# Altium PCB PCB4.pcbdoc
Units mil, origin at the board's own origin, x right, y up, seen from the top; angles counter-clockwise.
Board outline 4005 x 2740 mil, 2 copper layers (Top Layer, Bottom Layer), stack 2.757 mil thick; 56 components, 38 nets, 174 pads, 21 vias.
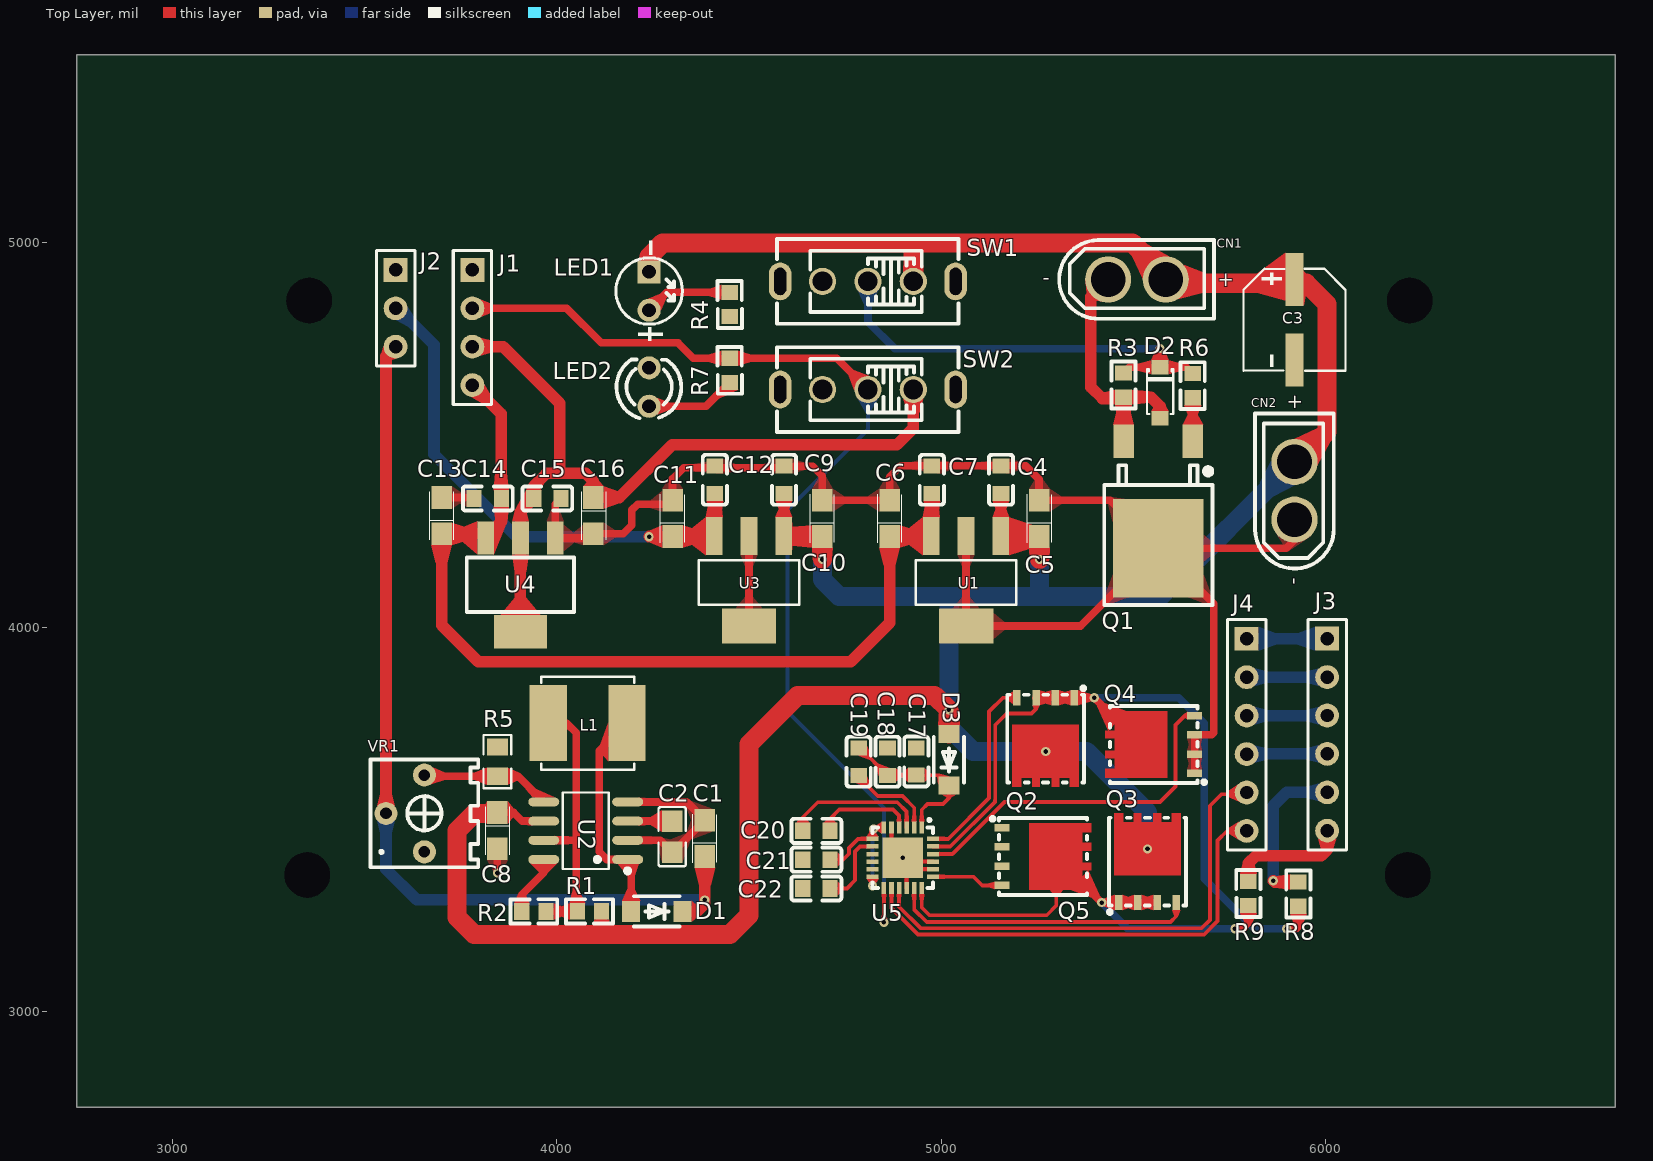
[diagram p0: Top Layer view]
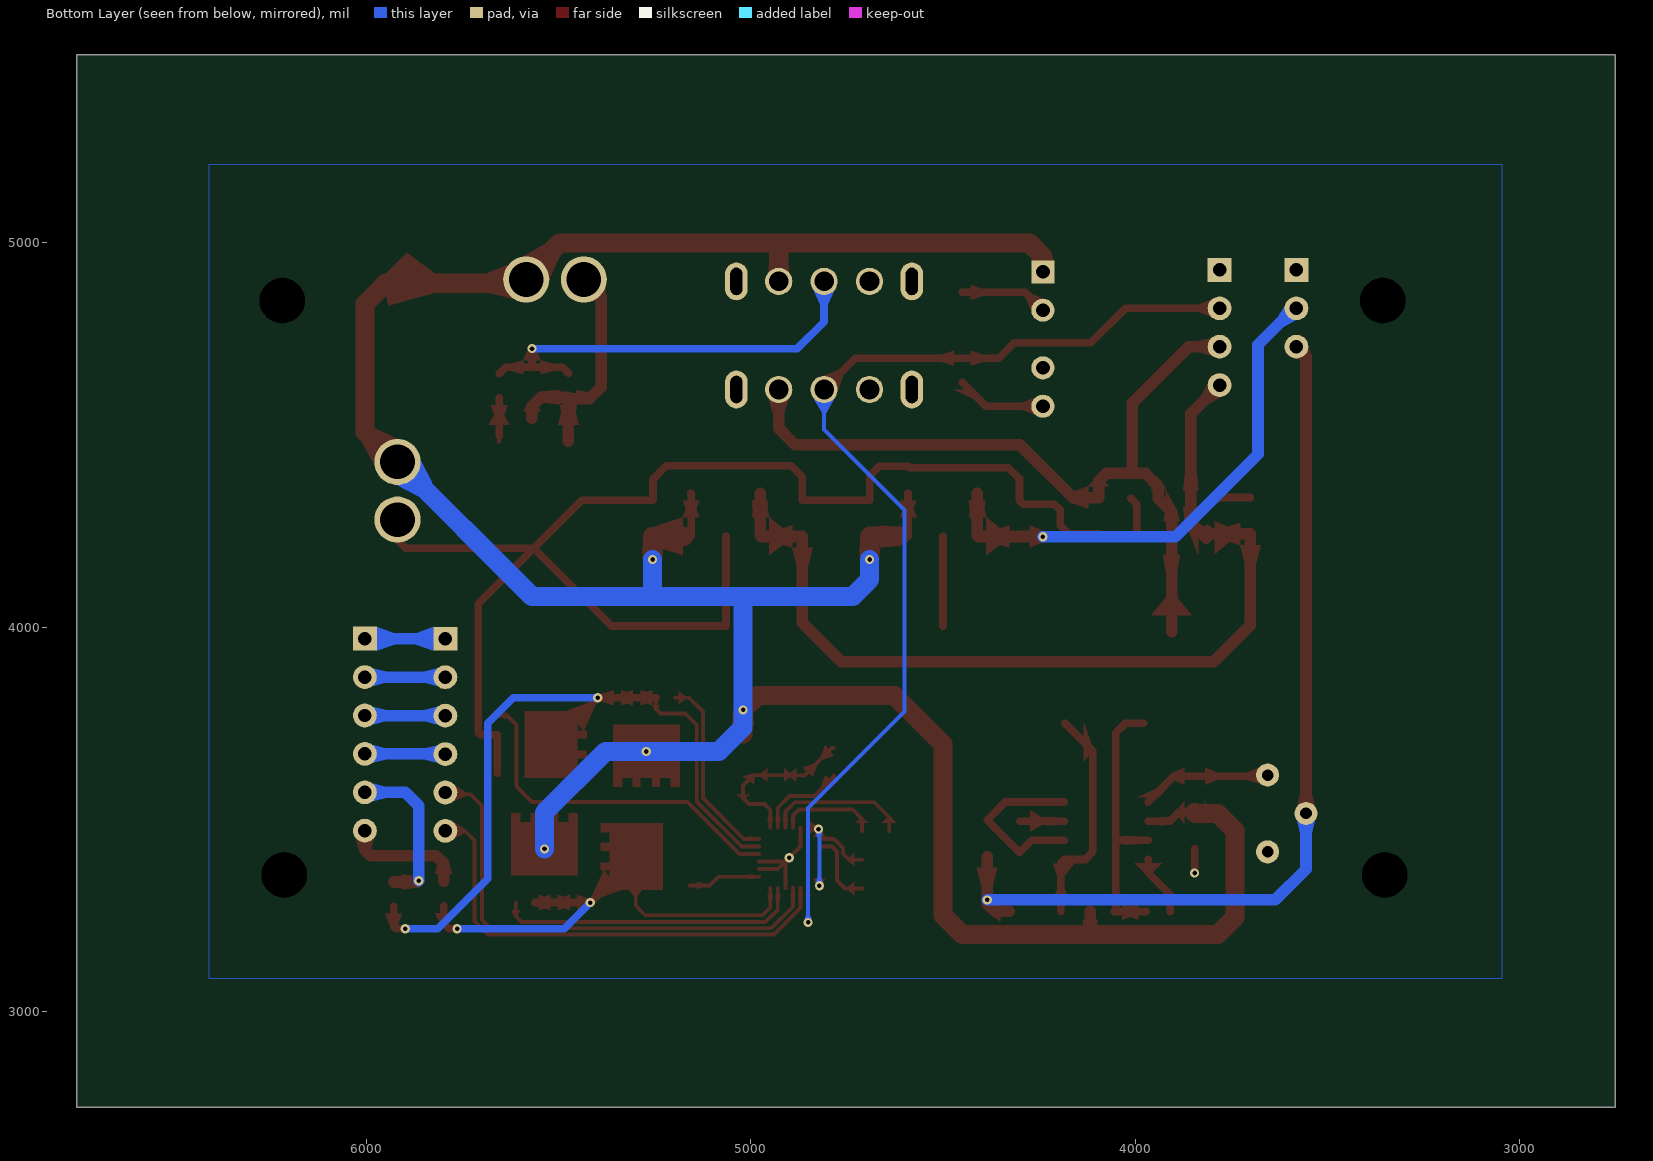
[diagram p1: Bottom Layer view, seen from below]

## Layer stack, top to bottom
Top Layer: signal copper 1.379
Bottom Layer: signal copper 1.378

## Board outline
6755,2750 2750,2750 2750,5490 6755,5490
cut-out: 3414.06,4850 ccw(c3355,4850) 3295.94,4850 ccw(c3355,4850)
cut-out: 6279.06,4850 ccw(c6220,4850) 6160.94,4850 ccw(c6220,4850)
cut-out: 6274.06,3355 ccw(c6215,3355) 6155.94,3355 ccw(c6215,3355)
cut-out: 3409.06,3355 ccw(c3350,3355) 3290.94,3355 ccw(c3350,3355)

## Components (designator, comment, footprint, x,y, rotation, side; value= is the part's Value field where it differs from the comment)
C1 "10u" CASE-A_3216 4385,3450 r90 top
C2 "470pF" C0805 4300,3454.45 r90 top
C3 "220uF" CAP-SMD_BD6.3-L6.6-W6.6-FD 5920,4800 r270 top
C4 "100nf" C0603 5156.02,4383.58 r270 top
C5 "10u" CASE-A_3216 5256.02,4283.14 r90 top
C6 "10u" CASE-A_3216 4866.02,4283.14 r90 top
C7 "100nf" C0603 4976.02,4383.58 r270 top
C8 "10u" CASE-A_3216 3845,3470 r270 top
C9 "100nf" C0603 4591.02,4383.58 r270 top
C10 "10u" CASE-A_3216 4691.02,4283.14 r90 top
C11 "10u" CASE-A_3216 4301.02,4283.14 r90 top
C12 "100nf" C0603 4411.02,4383.58 r270 top
C13 "10u" CASE-A_3216 3700,4290 r90 top
C14 "100nf" C0603 3820,4335 r0 top
C15 "100nf" C0603 3975,4335 r180 top
C16 "10u" CASE-A_3216 4095,4290 r270 top
C17 "100nF" C0603 4935.44,3650 r270 top
C18 "10uF" C0603 4860.44,3649.57 r270 top
C19 "16V 1uF" C0603 4785.44,3649.57 r270 top
C20 "100nF" C0603 4675.44,3469.57 r0 top
C21 "6.3V 1uF" C0603 4675.44,3394.57 r180 top
C22 "6.3V 1uF" C0603 4675.44,3319.57 r180 top
CN1 "XT30UPB-M" CONN-TH_XT30UPB-M 5510,4905 r0 top
CN2 "XT30UPB-M" CONN-TH_XT30UPB-M 5920,4355 r90 top
D1 "1N5819HW-7-F" SOD-123_L2.8-W1.8-LS3.7-FD 4260,3260 r0 top
D2 "BZT52C16_C216724" SOD-123_L2.8-W1.8-LS3.7-RD 5570,4610 r270 top
D3 "1N5819HW-7-F" SOD-123_L2.8-W1.8-LS3.7-FD 5020.44,3654.57 r270 top
J1 "HDR-M-2.54_1x4" HDR-M-2.54_1X4 3780,4780 r270 top
J2 "HDR-M-2.54_1x3" HDR-M-2.54_1X3 3580,4830 r270 top
J3 "HDR-M-2.54_1x6" HDR-M-2.54_1X6 6005,3720 r270 top
J4 "HDR-M-2.54_1x6" HDR-M-2.54_1X6 5795.44,3719.57 r270 top
L1 "470uH" IND-SMD_L6.0-W6.0_SWPA6045S 4080,3750 r180 top
LED1 "TJ-L3FYTGHGMCGLFLC2G-A5" LED-TH_BD3.9-P2.54-FD 4240,4875 r270 top
LED2 "TJ-L3FYTXHAMCGLFLC0A-A5" LED-TH_BD3.0-P2.54-FD 4240,4625 r90 top
Q1 "IRLR7843TRPBF" TO-252-2_L6.5-W6.1-P4.58-LS10.0-TR 5565.51,4344.55 r0 top
Q2 "TPH1R403NL" POWERVDFN-8_L6.2-W5.2-P1.27-LS6.0-BL 5272.24,3746.26 r180 top
Q3 "TPH1R403NL" POWERVDFN-8_L6.2-W5.2-P1.27-LS6.0-BL 5537.24,3352.88 r0 top
Q4 "TPH1R403NL" POWERVDFN-8_L6.2-W5.2-P1.27-LS6.0-BL 5590.32,3694.57 r90 top
Q5 "TPH1R403NL" POWERVDFN-8_L6.2-W5.2-P1.27-LS6.0-BL 5228.74,3402.76 r270 top
R1 "0.22R" R0603 4085,3260 r0 top
R2 "180R" R0603 3939.97,3259.8 r0 top
R3 "100k" R0603 5475,4630 r90 top
R4 "510" R0603 4450,4840 r90 top
R5 "1k" R0805 3845,3650 r270 top
R6 "1k" R0603 5655,4628.51 r90 top
R7 "330" R0603 4450,4668.51 r90 top
R8 "1k" R0603 5930,3305 r270 top
R9 "1k" R0603 5800,3306.49 r270 top
SW1 "SS-12F44-G5" SW-TH_SS-12F44-G5 4809.54,4900 r180 top
SW2 "SS-12F44-G5" SW-TH_SS-12F44-G5 4809.54,4618.54 r180 top
U1 "LM2940S-5.0" SOT-223-3_L6.5-W3.4-P2.30-LS7.0-BR 5065,4120 r90 top
U2 "MC34063ADR" SOIC-8_L4.9-W3.9-P1.27-LS6.0-BL 4075,3470 r90 top
U3 "LM2940S-5.0" SOT-223-3_L6.5-W3.4-P2.30-LS7.0-BR 4500,4120 r90 top
U4 "AMS1117-3.3_C347222" SOT-223_L6.7-W3.5-P2.30-BR 3905,4110 r90 top
U5 "DRV8701ERGET" VQFN-24_L4.0-W4.0-P0.50-LS4.0-BL-EP 4900.48,3399.51 r180 top
VR1 "10kΩ" RES-ADJ-TH_3362P 3605,3515 r90 top

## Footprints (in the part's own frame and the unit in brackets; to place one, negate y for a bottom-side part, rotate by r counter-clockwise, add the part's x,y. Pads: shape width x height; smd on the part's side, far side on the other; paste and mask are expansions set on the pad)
C0603 [mm]
  rect 1x1.1 smd: 1(-0.9,0) 2(0.9,0)
  silkscreen extent -1.65,-0.8 1.65,0.8
C0805 [mm]
  rect 1.41x1.35 smd: 1(-1.03,0) 2(1.03,0)
  silkscreen extent -1.96,-0.9 1.96,0.9
CAP-SMD_BD6.3-L6.6-W6.6-FD [mm]
  rect 3.5x1.2 smd: 1(-2.67,0) 2(2.67,0)
  silkscreen extent -3.38,-3.38 3.38,3.38
CASE-A_3216 [mil]
  rect 59.05x53.5 smd: 1(-47.24,0) 2(47.24,0)
  silkscreen extent -63,-32 63,32
CONN-TH_XT30UPB-M [mil]
  round 120 hole 90: 1(-74.99,0) 2(75.01,0)
  silkscreen extent -202,-102 201,102
HDR-M-2.54_1X3 [mil]
  rect 62x62 hole 35: 1(-100,0)
  round 62 hole 35: 2(0,0) 3(100,0)
  silkscreen extent -150,-50 150,50
HDR-M-2.54_1X4 [mil]
  rect 62x62 hole 35: 1(-150,0)
  round 62 hole 35: 2(-50,0) 3(50,0) 4(150,0)
  silkscreen extent -200,-50 200,50
HDR-M-2.54_1X6 [mil]
  rect 62x62 hole 35: 1(-250,0)
  round 62 hole 35: 2(-150,0) 3(-50,0) 4(50,0) 5(150,0) 6(250,0)
  silkscreen extent -300,-50 300,50
IND-SMD_L6.0-W6.0_SWPA6045S [mm]
  rect 2.474x5.02 smd: 1(-2.603,0) 2(2.603,0)
  silkscreen extent -3.08,-3.08 3.08,3.08
LED-TH_BD3.0-P2.54-FD [mil]
  round 60 hole 36: 1(-50,0) 2(50,0)
  silkscreen extent -81,-84 72,85
LED-TH_BD3.9-P2.54-FD [mil]
  rect 60x60 hole 36: 1(-50,0)
  round 60 hole 36: 2(50,0)
  silkscreen extent -130,-87 130,87
POWERVDFN-8_L6.2-W5.2-P1.27-LS6.0-BL [mm]
  rect 0.5x1 smd: 1(-1.905,-1.775) 2(-0.635,-1.775) 3(0.635,-1.775) 4(1.905,-1.775)
  Top Layer region: -2.2,0.025 -2.2,4.125 -1.6,4.125 -1.6,3.525 -0.9,3.525 -0.9,4.125 -0.4,4.125 -0.4,3.525 0.4,3.525 0.4,4.125 0.9,4.125 0.9,3.525 1.6,3.525 1.6,4.125 2.2,4.125 2.2,0.025
  silkscreen extent -2.61,-2.53 2.54,3.83
R0603 [mm]
  rect 1x1.1 smd: 1(-0.8,0) 2(0.8,0)
  silkscreen extent -1.55,-0.8 1.55,0.81
R0805 [mil]
  rect 44.59x54.21 smd: 1(-38.04,0) 2(38.04,0)
  silkscreen extent -69,-36 69,36
RES-ADJ-TH_3362P [mil]
  round 60 hole 30: 1(-100,-50) 2(0,50) 3(100,-50)
  silkscreen extent -140,-190 140,90
SOD-123_L2.8-W1.8-LS3.7-FD [mm]
  rect 1.2x1.4 smd: 1(-1.7,0) 2(1.7,0)
  silkscreen extent -1.5,-1 1.5,1
SOD-123_L2.8-W1.8-LS3.7-RD [mm]
  rect 0.95x1.15 smd: 1(-1.692,0) 2(1.692,0)
  silkscreen extent -1.58,-0.87 1.41,0.87
SOIC-8_L4.9-W3.9-P1.27-LS6.0-BL [mm]
  oval 0.588x2.045 smd: 1(-1.905,-2.772) 2(-0.635,-2.772) 3(0.635,-2.772) 4(1.905,-2.772) 5(1.905,2.772) 6(0.635,2.772) 7(-0.635,2.772) 8(-1.905,2.772)
  silkscreen extent -2.8,-2.92 2.53,1.52
SOT-223-3_L6.5-W3.4-P2.30-LS7.0-BR [mm]
  rect 2.5x1.1 smd: 1(2.97,-2.3) 2(2.97,0) 3(2.97,2.3)
  rect 2.34x3.6 smd: 4(-2.97,0)
  silkscreen extent -1.57,-3.33 1.37,3.33
SOT-223_L6.7-W3.5-P2.30-BR [mm]
  rect 2.2x1.1 smd: 1(3.099,-2.3) 2(3.099,0) 3(3.099,2.3)
  rect 2.2x3.5 smd: 4(-3.099,0)
  silkscreen extent -1.8,-3.55 1.8,3.55
SW-TH_SS-12F44-G5 [mm]
  round 1.8 hole 1.3: 1(-3,0) 2(0,0) 3(3,0)
  oval 1.5x2.5 hole 0.8 slot 1.8 at 90 deg: 4(5.8,0) 5(-5.8,0)
  silkscreen extent -6,-2.8 6,2.8
TO-252-2_L6.5-W6.1-P4.58-LS10.0-TR [mm]
  rect 1.35x2.2 smd: 1(2.29,3.533) 3(-2.29,3.533)
  rect 6x6.5 smd: 4(0,-3.533)
  silkscreen extent -3.57,-7.3 3.57,1.95
VQFN-24_L4.0-W4.0-P0.50-LS4.0-BL-EP [mm]
  rect 0.3x0.8 smd: 1(-1.25,-1.999) 2(-0.751,-2) 3(-0.25,-2) 4(0.25,-2) 5(0.751,-2) 6(1.251,-2) 13(1.25,2) 14(0.749,2) 15(0.249,2) 16(-0.25,2) 17(-0.749,2) 18(-1.25,2)
  rect 0.8x0.3 smd: 7(2.001,-1.25) 8(2.001,-0.75) 9(2.001,-0.249) 10(2.001,0.251) 11(2.001,0.752) 12(2.001,1.251) 19(-2.001,1.25) 20(-2.001,0.75) 21(-2.001,0.251) 22(-2.001,-0.248) 23(-2.001,-0.749) 24(-2.001,-1.249)
  rect 2.7x2.7 smd: 25(0.001,-0.002)
  silkscreen extent -2,-2.6 2,2

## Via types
v1: diameter 24.02, hole 12.01, Top Layer to Bottom Layer, 21 vias

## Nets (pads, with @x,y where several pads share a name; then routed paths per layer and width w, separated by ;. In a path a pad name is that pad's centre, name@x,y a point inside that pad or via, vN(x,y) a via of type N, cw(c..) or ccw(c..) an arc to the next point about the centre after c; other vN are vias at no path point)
$1N55: R5.2 U2.5 VR1.3 | length 339.8
  Top Layer w20: VR1.3 3658.04,3611.96 R5.2 3898.89,3611.96 U2.5
$1N212: L1.2 R1.1 R2.2 U2.7 | length 715.7
  Top Layer w20: U2.7 4050,3445 ; R2.2 R1.1@4053.3,3259.8 ; L1.2 4025,3750 4050,3725 4050,3445 ; R1.1 R1.1@4053.3,3259.8 ; 4050,3445 4050,3263.1 R1.1@4053.3,3259.8
$1N213: R2.1 U2.8 | length 159
  Top Layer w20: R2.1 3908.48,3303.48 3965.85,3360.85 U2.8
$1N218: C2.2 U2.3 | length 115.9
  Top Layer w20: U2.3 C2.2
$1N221: D1.1 L1.1 U2.1 | length 586.2
  Top Layer w20: L1.1 4110,3677.52 4110,3415 4130,3395 U2.1 4193.07,3386.08 D1.1
$1N479: Q1.1 R6.1 | length 113.6
  Top Layer w10: Q1.1@5655,4497.16 5655,4484.32 Q1.1
  Top Layer w20: Q1.1@5655,4497.16 R6.1
$1N482: D2.1 R3.2 R6.2 SW1.2 | length 1135.7
  Top Layer w10: D2.1 D2.1@5576.64,4676.63
  Top Layer w20: R3.2 5490.14,4676.63 D2.1 v1(5570,4725) ; D2.1@5576.64,4676.63 5638.37,4676.63 R6.2
  Bottom Layer w20: SW1.2 4809.54,4795.46 4880,4725 v1(5570,4725)
$1N610: LED1.2 R4.2 | length 229.3
  Top Layer w20: LED1.2 4286.49,4871.49 R4.2
$1N637: LED2.1 R7.1 | length 235.7
  Top Layer w20: LED2.1 4387.99,4575 R7.1
$1N34558: C21.1 U5.6 U5.7 U5.12 | length 370.8
  Top Layer w10: C21.1 4744.57,3394.57 4760,3410 4760,3425 4783.72,3448.72 U5.7 4820,3450.43 4820,3470 4828.25,3478.25 U5.6 ; v1(4821.72,3326.72) U5.12
  Bottom Layer w10: v1(4821.72,3326.72) 4821.72,3471.72 v1(4824.19,3474.19)
$1N34565: C20.2 U5.4 | length 258.6
  Top Layer w10: C20.2 4710.87,3500.87 4735,3525 4875,3525 4890.62,3509.38 U5.4
$1N34566: C20.1 U5.3 | length 373.4
  Top Layer w10: C20.1 4640,3505 4679,3544 4886,3544 4910.34,3519.66 U5.3
$1N34567: C19.2 U5.2 | length 233.9
  Top Layer w10: C19.2 4785.44,3609.57 4835,3560 4900,3560 4930.02,3529.97 U5.2
$1N34568: C17.2 C18.2 C19.1 D3.2 U5.1 | length 437.8
  Top Layer w10: C19.1 4789.56,3685 C18.2 4860.87,3614.57 C17.2 4993.51,3614.57 D3.2 5020.44,3555.43 5005,3540 4965,3540 4949.69,3524.68 U5.1
$1N34570: Q2.4 U5.24 | length 502
  Top Layer w10: U5.24 5018.69,3448.69 5125,3555 5125,3780 5161.14,3816.14 Q2.4
$1N34571: Q4.4 U5.22 | length 923.9
  Top Layer w10: U5.22 5029.29,3409.29 5165,3545 5570,3545 5610,3585 5610,3745 5634.57,3769.57 Q4.4
$1N34574: Q3.4 U5.17 | length 793.5
  Top Layer w10: U5.17 4929.98,3265.03 4962.69,3232.31 5597.31,3232.31 5612.24,3247.24 Q3.4
$1N34575: Q5.4 U5.19 | length 189
  Top Layer w10: U5.19 4979.52,3350 5085,3350 5107.24,3327.76 Q5.4
ADC-0: J3.1 J4.1 | length 209.7
  Bottom Layer w30: J4.1 6004.57,3969.57 J3.1
ADC-1: J3.2 J4.2 | length 209.7
  Bottom Layer w30: J4.2 6004.57,3869.57 J3.2
ADC-2: J3.3 J4.3 | length 209.7
  Bottom Layer w30: J4.3 6004.57,3769.57 J3.3
ADC-3: J3.4 J4.4 | length 209.7
  Bottom Layer w30: J4.4 5795.87,3670 J3.4
AOUT+: Q2.1 Q2.2 Q2.3 R8.2 U5.23 | length 1960.5
  Top Layer w10: U5.23 5023.99,3428.99 5140,3545 5140,3549.43 5141,3548.37 5141,3745 5171,3775 5235,3775 5247.24,3787.24 Q2.3
  Top Layer w20: Q2.3 Q2.2 Q2.1 v1(5398.86,3816.14) 5520.44,3694.57 ; v1(5900,3215) 5925,3215 5930,3220 R8.2
  Bottom Layer w20: v1(5398.86,3816.14) 5618.86,3816.14 5685,3750 5685,3345 5815,3215 v1(5900,3215)
AOUT+OUT: J3.5 R8.1 | length 415.9
  Top Layer w30: v1(5865,3340) 5868.5,3336.5 R8.1
  Bottom Layer w30: v1(5865,3340) 5865,3535 5900,3570 J3.5
AOUT-: Q3.1 Q3.2 Q3.3 R9.2 U5.18 | length 1320.1
  Top Layer w10: U5.18 4949.68,3270.32 4970,3250 5275,3250 5300,3275 5300,3401.39
  Top Layer w20: 5298.63,3402.76 5300,3401.39 v1(5418.4,3282.99) Q3.1 Q3.2 Q3.3 ; v1(5765,3215) 5785,3215 5800,3230 R9.2
  Bottom Layer w20: v1(5418.4,3282.99) 5486.39,3215 v1(5765,3215)
AOUT-OUT: J3.6 R9.1 | length 316.5
  Top Layer w30: R9.1 5800,3385 5820,3405 5990,3405 6005,3420 J3.6
DVDD: C22.1 U5.8 | length 200.1
  Top Layer w10: C22.1 4711.3,3320 4755,3320 4776,3341 4776,3416 4789.02,3429.02 U5.8
EN: J4.6 U5.14 | length 1239.8
  Top Layer w10: U5.14 4870.98,3269.03 4940,3200 5685,3200 5720,3235 5720,3445 5745,3470 5795,3470 J4.6
GND: C1.2 C2.1 C3.2 C4.1 C5.2 C6.2 C7.1 C8.2 C9.1 C10.2 C11.2 C12.1 C13.2 C14.1 C15.1 C16.2 C17.1 C18.1 C21.2 C22.2 CN2.1 J1.1 J2.1 LED2.2 Q1.4 Q4.1 Q4.2 Q4.3 Q5.1 Q5.2 Q5.3 R4.1 R5.1 U1.2 U1.4 U2.2 U2.4 U3.2 U3.4 U4.1 U5.5 U5.16 U5.20 U5.21 U5.25 | length 5145.2
  Top Layer w10: U5.5 4870.93,3429.08 v1(4900.44,3399.57) U5.25@4910.32,3389.68 ; U5.16 U5.25@4910.32,3389.68 ; U5.21@4979.19,3389.68 U5.25@4910.32,3389.68 ; U5.20 4930.02,3369.99 U5.25@4910.32,3389.68
  Top Layer w20: C13.2 3782.32,4337.24 C14.1 ; v1(3845,3360) C8.2 ; C15.1 3995.55,4320.11 U4.1 4084.24,4232 C16.2 4172.76,4242.76 4195,4265 4195,4305 4210,4320 4290.64,4320 C11.2 4301.02,4386.02 4330,4415 4587.01,4415 C9.1 4665.99,4419.01 4691.02,4393.98 C10.2 C6.2 4866.02,4391.02 4895,4420 5220,4420 5255,4385 5255,4331.4 C5.2 5440.58,4330.38 Q1.4 ; U2.2 4268.9,3445 C2.1 4301.66,3413.9 C1.2 4337.24,3545 U2.4 ; U3.4 U3.2 ; U1.2 U1.4 5363.14,4003.07 Q1.4 ; Q4.1 Q4.2 Q4.3 5704.57,3719.57 5710,3725 5710,4060.96 Q1.4 ; CN2.1@5935,4241.57 5898.87,4205.45 Q1.4
GNDIN: CN1.1 D2.2 Q1.3 R3.1 | length 647.4
  Top Layer w30: CN1.1 5390,4860 5390,4625 5420,4595 R3.1@5475,4595 ; Q1.3 5475,4484 R3.1@5475,4595 ; D2.2 5570,4575 5546.5,4598.5 R3.1 R3.1@5475,4595
NSLEEP: J1.2 R7.2 SW2.2 U5.13 | length 2784.8
  Top Layer w10: v1(4851.27,3231.28) U5.13
  Top Layer w20: J1.2 4025,4830 4115,4740 4315,4740 4355,4700 R7.2 4728.07,4700 SW2.2
  Bottom Layer w10: SW2.2 4809.54,4514.54 4600,4305 4600,3780 4851.27,3528.72 v1(4851.27,3231.28)
PH: J4.5 U5.15 | length 1297.1
  Top Layer w10: U5.15 4890.68,3271.95 4946.31,3216.31 5678.69,3216.31 5700,3237.63 5700,3535 5730,3565 5790.87,3565 J4.5
VCC: C3.1 C4.2 C5.1 C8.1 C9.2 C10.1 CN1.2 CN2.2 D3.1 LED1.1 R1.2 SW1.1 U1.1 U2.6 U3.1 | length 8033.9
  Top Layer w20: 3815,3515 3817.24,3517.24 ; C8.1 3887.76,3517.24 3910,3495 U2.6 ; C9.2 4591.02,4237.4 U3.1 4612.54,4236.93 ; v1@4690,4175 v1(4691.02,4176.02) ; SW1.1 SW1.1@4927.65,4917.65 ; C4.2 5155.55,4347.67 U1.1 5156.57,4235.9 U1.1@5174.63,4235.9 ; v1@5255,4175 v1(5256.02,4176.02)
  Top Layer w30: 4116.18,3200 4116.49,3200.31 R1.2 ; CN1.2 CN1.2@5593.43,4905 ; 5701.27,4905 5711.27,4895
  Top Layer w50: C8.1 3842.76,3515 3815,3515 3785,3515 3740,3470 3740,3245 3785,3200 4116.18,3200 4450,3200 4500,3250 4500,3695 4627.12,3822.12 4982.88,3822.12 v1(5020.44,3784.57) D3.1 ; v1(4240,4925) 4240,4965 4275,5000 4931.95,5000 ; 4612.54,4236.93 4690,4236.93 C10.1 v1(4691.02,4176.02) ; SW1.1@4927.65,4917.65 4927.65,4995.7 4931.95,5000 ; U1.1@5174.63,4235.9 C5.1 v1(5256.02,4176.02) ; CN2.2@5935,4438.43 6005,4508.43 6005,4840.7 5950.7,4895 5711.27,4895 v1(5603.43,4895) 5593.43,4905 5498.43,5000 4931.95,5000
  Bottom Layer w50: v1(4691.02,4176.02) 4691.02,4123.98 4735,4080 5029.27,4080 ; v1(5256.02,4176.02) 5256.02,4080 ; v1(5537.24,3422.76) 5537.24,3517.76 5378.63,3676.37 v1(5272.24,3676.37) 5083.63,3676.37 5020.44,3739.57 v1(5020.44,3784.57) 5020.44,4071.16 5029.27,4080 ; CN2.2@5935,4438.43 5928.43,4438.43 5570,4080 5256.02,4080 ; 5029.27,4080 5256.02,4080
  other v1: 4240,4925
VCC3V3: C15.2 C16.1 J1.3 SW2.1 U4.2 U4.4 | length 2092.6
  Top Layer w20: C16.1 C16.1@4107.54,4337.24
  Top Layer w30: J1.3 3860,4730 4007.17,4582.83 4007.17,4400 ; U4.4 U4.2 3905,4300.44 C15.2 3939.57,4366.91 3972.65,4400 4007.17,4400 ; C16.1 4095,4380 4075,4400 4007.17,4400 ; C16.1@4107.54,4337.24 4162.24,4337.24 4300,4475 4885,4475 4927.65,4517.65 SW2.1
VCC5V_BOARD: C6.1 C7.2 C13.1 C14.2 J1.4 U1.3 U4.3 | length 2510
  Top Layer w30: J1.4 3855,4555 3855,4335.44 C14.2 3855.43,4272.98 U4.3@3822.69,4240.24 ; U4.3@3811.93,4251 U4.3@3820.17,4242.76 ; U4.3 U4.3@3822.69,4240.24 ; U1.3 4973.43,4235.9 C6.1 4866.02,4011.02 4765,3910 3795,3910 3700,4005 C13.1 U4.3@3820.17,4242.76 ; U1.3@4976.02,4238.5 C7.2 ; U4.3@3820.17,4242.76 U4.3@3822.69,4240.24
VCC5V_OUT: C11.1 C12.2 J2.2 U3.3 | length 1361.3
  Top Layer w30: v1@4240.9,4235.9 C11.1 4408.43,4235.9 4411.02,4238.5 C12.2
  Bottom Layer w20: J2.2 J2.2@3585,4830 ; 3680,4735 3685,4730
  Bottom Layer w30: J2.2@3585,4830 3680,4735 3680,4450 3895,4235 v1(4240,4235)
VCC10V: C1.1 D1.2 J2.3 VR1.2 | length 2422.6
  Top Layer w20: J2.3@3571.66,4721.66 J2.3
  Top Layer w30: VR1.2 3555,4705 J2.3@3571.66,4721.66 ; D1.2 4365,3260 4385,3280 v1(4385,3290) C1.1
  Bottom Layer w30: VR1.2 3555,3370 3635,3290 v1(4385,3290)
"": SW1.3 SW1.4 SW1.5 SW2.3 SW2.4 SW2.5 U5.9 U5.10 U5.11 VR1.1

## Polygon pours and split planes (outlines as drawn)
GND on Bottom Layer (solid, remove dead copper, pour order 0): 3045,3085 6410,3085 6410,5205 3045,5205
GND on Top Layer (solid, remove dead copper, pour order 1): 3000,3000 6505,3000 6505,5240 3000,5240

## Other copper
Top Layer:
  region net VCC5V_BOARD: 3685,4168.23 3715,4168.23 3726.75,4213.23 3673.25,4213.23
  region net VCC5V_BOARD: 3771.75,4257.76 3726.75,4272.29 3726.75,4213.23 3771.75,4227.76
  region net VCC3V3: 4162.24,4322.24 4162.24,4352.24 4121.75,4366.77 4121.75,4307.71
  region net VCC3V3: 4080,4380 4068.25,4366.77 4121.75,4366.77 4110,4380
  region net VCC: 3815,3540 3815,3490 3818.25,3487.71 3818.25,3546.77
  region net VCC: 3887.76,3527.24 3871.75,3546.77 3871.75,3487.71 3887.76,3507.24
  region net VCC10V: 4400,3328.23 4411.75,3373.23 4358.25,3373.23 4370,3328.23
  region net VCC3V3: 3920,4076.31 3890,4076.31 3852.5,4031.31 3957.5,4031.31
  region net VCC5V_BOARD: 3747.8,4257.76 3747.8,4227.76 3792.8,4190.26 3792.8,4275.31
  region net VCC5V_BOARD: 3866.04,4262.38 3844.83,4283.59 3836.1,4275.31 3836.1,4188.69
  region net VCC3V3: 3920,4143.69 3926.65,4188.69 3883.35,4188.69 3890,4143.69
  region net VCC3V3: 3890,4300.44 3883.35,4275.31 3926.65,4275.31 3920,4300.44
  region net VCC5V_BOARD: 3840,4401.65 3835.75,4356.65 3875.12,4356.65 3870,4401.65
  region net VCC5V_BOARD: 3870.43,4272.98 3875.12,4313.35 3835.75,4313.35 3840.43,4272.98
  region net VCC3V3: 3894.39,4311.04 3915.61,4289.83 3919.88,4313.35 3919.88,4356.65
  region net VCC3V3: 3954.57,4366.91 3924.57,4366.91 3919.88,4356.65 3959.25,4356.65
  region net $1N55: 3787.89,3601.96 3817.89,3589.67 3817.89,3634.25 3787.89,3621.96
  region net $1N55: 3898.89,3621.96 3872.11,3634.25 3872.11,3589.67 3898.89,3601.96
  region net $1N221: 4203.07,3317.56 4183.07,3317.56 4169.45,3287.56 4216.69,3287.56
  region net VCC10V: 4365,3245 4365,3275 4350.55,3287.56 4350.55,3232.44
  region net $1N218: 4243.43,3485 4273.43,3467.24 4273.43,3522.76 4243.43,3505
  region net $1N212: 4021.15,3269.8 3991.15,3281.45 3991.15,3238.15 4021.15,3249.8
  region net $1N213: 3918.48,3303.48 3898.48,3303.48 3888.79,3281.45 3928.16,3281.45
  region net VCC: 4131.49,3200.31 4136.18,3238.35 4096.81,3238.35 4101.49,3200.31
  region net $1N212: 4003.82,3269.8 4003.82,3249.8 4033.82,3238.35 4033.82,3281.65
  region net $1N212: 4060,3311.65 4040,3311.65 4033.82,3281.65 4073.19,3281.65
  region net $1N221: 4130,3405 4130,3385 4155.47,3383.43 4155.47,3406.57
  region net $1N221: 4203.07,3353.43 4212.83,3383.43 4158.07,3383.43 4183.07,3353.43
  region net $1N218: 4248.66,3485 4248.66,3505 4212.83,3506.57 4212.83,3483.43
  region net $1N213: 3975.85,3360.85 4000.85,3385.3 3930.85,3385.3 3955.85,3360.85
  region net $1N212: 4030.36,3435 4030.36,3455 3994.53,3456.57 3994.53,3433.43
  region net VCC: 3910,3505 3910,3485 3937.17,3483.43 3937.17,3506.57
  region net $1N55: 3947.2,3577.79 3918.92,3577.79 3937.17,3556.57 3994.53,3556.57
  region net VCC10V: 3549.06,4731.94 3544.39,4715.61 3565.61,4694.39 3581.94,4699.06
  region net VCC: 4954.22,4923.44 4952.65,4960.24 4902.65,4960.24 4901.07,4923.44
  region net GNDIN: 5585,4575 5555,4575 5547.36,4562.07 5592.64,4562.07
  region net $1N482: 5517.36,4666.63 5547.36,4657.93 5547.36,4695.33 5517.36,4686.63
  region net $1N482: 5622.64,4666.63 5622.64,4686.63 5592.64,4695.33 5592.64,4657.93
  region net $1N482: 5560,4725 5547.36,4695.33 5592.64,4695.33 5580,4725
  region net GNDIN: 5490,4571.95 5460,4571.95 5448.78,4526.95 5501.93,4526.95
  region net $1N479: 5665,4556.95 5645,4556.95 5629.1,4526.95 5682.25,4526.95
  region net $1N479: 5665,4547.32 5676.65,4577.32 5633.35,4577.32 5645,4547.32
  region net GNDIN: 5490,4533.82 5496.65,4578.82 5453.35,4578.82 5460,4533.82
  region net GNDIN: 5420,4610 5420,4580 5453.35,4578.82 5453.35,4618.19
  region net GNDIN: 5541.65,4613.5 5496.65,4618.19 5496.65,4578.82 5541.65,4583.5
  region net VCC3V3: 4901.07,4595.1 4912.65,4558.3 4942.65,4558.3 4954.22,4595.1
  region net NSLEEP: 4811.76,4653.9 4774.01,4668.2 4759.87,4654.06 4774.17,4616.32
  region net NSLEEP: 3800.5,4806.75 3832.7,4820 3832.7,4840 3800.5,4853.25
  region net VCC3V3: 3800.5,4706.75 3832.7,4715 3832.7,4745 3800.5,4753.25
  region net VCC5V_BOARD: 3778.06,4599.06 3806.66,4582.13 3827.87,4603.34 3810.94,4631.94
  region net VCC: 4215,4965 4210,4955 4270,4955 4265,4965
  region net $1N610: 4269.94,4823.12 4283.13,4853.99 4268.99,4868.13 4238.12,4854.94
  region net $1N610: 4398.35,4861.49 4428.35,4851.81 4428.35,4891.18 4398.35,4881.49
  region net NSLEEP: 4501.65,4710 4471.65,4719.69 4471.65,4680.31 4501.65,4690
  region net NSLEEP: 4398.35,4710 4398.35,4690 4428.35,4680.31 4428.35,4719.69
  region net $1N637: 4423.24,4596.11 4471.65,4617.32 4428.35,4617.32 4407.13,4608.29
  region net $1N637: 4259.84,4552.5 4291,4565 4291,4585 4259.84,4597.5
  region net AOUT-OUT: 5981.75,3449.5 5990,3420 6020,3420 6028.25,3449.5
  region net EN: 5775.26,3493.1 5745,3475 5745,3465 5774.61,3446.61
  region net PH: 5771.73,3589.54 5742.09,3570 5743.58,3560 5778.58,3543.55
  region net VCC: 5252.2,4210.9 5252.2,4260.9 5177.2,4286.14 5177.2,4187.71
  region net VCC: 5145.55,4316.14 5133.9,4286.14 5177.2,4286.14 5165.55,4316.14
  region net VCC5V_BOARD: 4907.8,4220.9 4952.8,4187.71 4952.8,4286.14 4907.8,4250.9
  region net VCC5V_BOARD: 4991.02,4331.14 4961.02,4331.14 4952.8,4286.14 4996.1,4286.14
  region net VCC: 5174.63,4210.9 5229.27,4206.38 5229.27,4265.43 5174.63,4260.9
  region net VCC: 5281.02,4176.02 5282.77,4206.38 5229.27,4206.38 5231.02,4176.02
  region net VCC5V_BOARD: 4881.02,4161.38 4892.77,4206.38 4839.27,4206.38 4851.02,4161.38
  region net VCC5V_BOARD: 4937.77,4220.9 4937.77,4250.9 4892.77,4265.43 4892.77,4206.38
  region net VCC: 5821.38,4920 5821.38,4870 5943.62,4836.22 5896.38,4974.02
  region net VCC: 5950.7,4920 5896.38,4974.02 5943.62,4836.22 5950.7,4870
  region net VCC5V_BOARD: 4991.02,4283.46 4997.67,4328.46 4954.37,4328.46 4961.02,4283.46
  region net VCC: 5145.55,4298.46 5165.55,4298.46 5177.67,4328.46 5134.37,4328.46
  region net $1N221: 4117.07,3670.45 4133.78,3651.18 4133.78,3750.8 4112.57,3694.23
  region net $1N55: 3672.46,3590.61 3704.94,3601.96 3706.97,3621.96 3677.02,3635.37
  region net VCC10V: 3577.5,3534.84 3570,3566 3540,3566 3532.5,3534.84
  region net VCC5V_OUT: 4426.02,4283.46 4432.67,4328.46 4389.37,4328.46 4396.02,4283.46
  region net VCC: 4601.02,4298.46 4612.67,4328.46 4569.37,4328.46 4581.02,4298.46
  region net VCC: 4612.54,4246.93 4612.2,4271.93 4612.2,4201.93 4612.54,4226.93
  region net VCC: 4601.02,4316.14 4581.02,4316.14 4568.9,4286.14 4612.2,4286.14
  region net VCC5V_OUT: 4342.8,4250.9 4342.8,4220.9 4387.8,4187.71 4387.8,4286.14
  region net VCC5V_OUT: 4426.02,4331.14 4396.02,4331.14 4387.8,4286.14 4431.1,4286.14
  region net VCC: 4716.02,4176.02 4717.77,4206.38 4664.27,4206.38 4666.02,4176.02
  region net VCC: 4612.54,4211.93 4664.27,4206.38 4664.27,4265.43 4612.54,4261.93
  region net VCC5V_OUT: 4240.9,4220.9 4274.27,4206.38 4274.27,4265.43 4240.9,4250.9
  region net VCC5V_OUT: 4372.77,4250.9 4327.77,4265.43 4327.77,4206.38 4372.77,4220.9
  region net $1N34568: 4944.69,3508.98 4943.78,3493.98 4955.59,3493.98 4954.69,3508.98
  region net $1N34567: 4925.02,3509 4924.12,3494 4935.93,3494 4935.02,3509
  region net $1N34566: 4905.34,3509 4904.43,3494 4916.24,3494 4915.34,3509
  region net $1N34565: 4885.62,3509 4884.72,3494 4896.53,3494 4895.62,3509
  region net $1N34558: 4830.33,3473.25 4845.33,3462.5 4845.33,3494 4830.33,3483.25
  region net $1N34558: 4825,3469.62 4815,3469.62 4805.97,3454.62 4837.46,3454.62
  region net $1N34558: 4790.97,3443.72 4805.97,3442.81 4805.97,3454.62 4790.97,3453.72
  region net DVDD: 4790.97,3424.02 4805.97,3423.11 4805.97,3434.92 4790.97,3434.02
  region net $1N34558: 4826.72,3329.36 4837.46,3344.36 4805.97,3344.36 4816.72,3329.36
  region net NSLEEP: 4846.27,3290.02 4856.27,3290.02 4857.18,3305.02 4845.37,3305.02
  region net EN: 4865.98,3290.02 4875.98,3290.02 4876.88,3305.02 4865.07,3305.02
  region net PH: 4885.68,3290.02 4895.68,3290.02 4896.58,3305.02 4884.77,3305.02
  region net $1N34574: 4934.98,3290.02 4935.88,3305.02 4924.07,3305.02 4924.98,3290.02
  region net AOUT-: 4954.68,3290.02 4955.58,3305.02 4943.77,3305.02 4944.68,3290.02
  region net $1N34575: 5009.98,3345 5009.98,3355 4994.98,3356.19 4994.98,3344.38
  region net $1N34571: 5009.98,3414.29 4994.98,3415.19 4994.98,3403.38 5009.98,3404.29
  region net AOUT+: 5009.98,3433.99 4994.98,3434.89 4994.98,3423.08 5009.98,3423.99
  region net $1N34570: 5009.98,3443.69 5009.98,3453.69 4994.98,3454.59 4994.98,3442.78
  region net $1N34558: 4744.57,3389.57 4744.57,3399.57 4730.56,3412.07 4730.56,3377.07
  region net DVDD: 4745.56,3315 4745.56,3325 4730.56,3337.5 4730.56,3302.5
  region net $1N34566: 4645,3505 4635,3505 4622.5,3491.22 4657.5,3491.22
  region net $1N34565: 4715.87,3500.87 4705.87,3500.87 4693.37,3491.22 4728.37,3491.22
  region net $1N34568: 4812.79,3654.71 4817.7,3663.95 4807.09,3692.23 4784.5,3665.32
  region net $1N34567: 4804.09,3583.84 4817.7,3584.38 4807.09,3612.66 4775.8,3594.45
  region net $1N34568: 4897.09,3609.57 4897.09,3619.57 4882.09,3632.07 4882.09,3597.07
  region net $1N34568: 4828.17,3639.32 4838.78,3611.04 4865.5,3633.82 4837.21,3644.43
  region net $1N34568: 4898.78,3609.57 4913.78,3597.07 4913.78,3632.07 4898.78,3619.57
  region net $1N34568: 4972.09,3609.57 4972.09,3619.57 4957.09,3632.07 4957.09,3597.07
  region net VCC: 4995.44,3784.57 4992.88,3745.12 5047.99,3745.12 5045.44,3784.57
  region net $1N34568: 5015.44,3555.43 5025.44,3555.43 5037.94,3564.02 5002.94,3564.02
  region net $1N34568: 4989.97,3611.03 4992.88,3590.45 5021.56,3611.26 4997.04,3618.1
  region net AOUT+: 5387.09,3826.14 5357.09,3835.83 5357.09,3796.46 5387.09,3806.14
  region net AOUT+: 5307.4,3826.14 5307.4,3806.14 5337.4,3796.46 5337.4,3835.83
  region net AOUT+: 5257.4,3826.14 5257.4,3806.14 5287.4,3796.46 5287.4,3835.83
  region net AOUT+: 5337.09,3826.14 5307.09,3835.83 5307.09,3796.46 5337.09,3806.14
  region net AOUT+: 5242.24,3787.24 5252.24,3787.24 5257.09,3796.46 5237.4,3796.46
  region net AOUT+: 5287.09,3826.14 5257.09,3835.83 5257.09,3796.46 5287.09,3806.14
  region net $1N34570: 5172.4,3811.14 5187.4,3798.64 5187.4,3833.64 5172.4,3821.14
  region net AOUT-: 5502.08,3272.99 5502.08,3292.99 5472.08,3302.68 5472.08,3263.31
  region net AOUT-: 5422.4,3272.99 5452.4,3263.31 5452.4,3302.68 5422.4,3292.99
  region net AOUT-: 5472.4,3272.99 5502.4,3263.31 5502.4,3302.68 5472.4,3292.99
  region net AOUT-: 5552.08,3272.99 5552.08,3292.99 5522.08,3302.68 5522.08,3263.31
  region net AOUT-: 5522.4,3272.99 5552.4,3263.31 5552.4,3302.68 5522.4,3292.99
  region net $1N34574: 5617.24,3248.31 5622.08,3263.31 5602.4,3263.31 5607.24,3248.31
  region net $1N34575: 5124.17,3322.76 5139.17,3317.92 5139.17,3337.61 5124.17,3332.76
  region net $1N34571: 5634.57,3774.57 5634.57,3764.57 5640.52,3759.73 5640.52,3779.41
  region net AOUT+: 5920,3223.82 5940,3223.82 5951.65,3253.82 5908.35,3253.82
  region net AOUT+OUT: 5868.5,3321.5 5908.35,3316.81 5908.35,3356.18 5868.5,3351.5
  region net AOUT-: 5790,3230 5810,3230 5821.65,3255.32 5778.35,3255.32
  region net AOUT-OUT: 5785,3385 5778.35,3357.68 5821.65,3357.68 5815,3385
  region net VCC: 5979.41,4421.61 6011.68,4479.75 5979.07,4517.85 5920.89,4489.99
  region net GNDIN: 5375.12,4908.76 5379.39,4870.61 5400.61,4849.39 5438.76,4845.12
  region net VCC: 5594.68,4964.21 5536.59,4997.19 5497.71,4965.36 5525.04,4907.21
  region net VCC: 5616.63,4854.02 5682.53,4870 5690.98,4920 5631.63,4942.76
  region net AOUT-: 5295,3301.15 5305,3301.15 5317.5,3316.15 5282.5,3316.15
  region net AOUT-: 5392.31,3294.94 5412.35,3303.18 5383.56,3367.33 5335.74,3316.15
  region net AOUT+: 5426.75,3802.4 5406.71,3794.16 5435.5,3730 5483.32,3781.18
  region net $1N34558: 4812.98,3469.88 4815,3455.82 4825,3452.1 4829.86,3463.6
  region net $1N34558: 4834.71,3468.4 4846.22,3473.25 4842.62,3483.25 4828.61,3485.35
  region net $1N34558: 4830.72,3334.66 4826.72,3347.13 4816.72,3347.13 4812.71,3334.66
  region net NSLEEP: 4860.28,3239.22 4856.27,3251.69 4846.27,3251.69 4842.27,3239.22
Bottom Layer:
  region net VCC5V_OUT: 3581.6,4799.04 3610.33,4783.45 3629.11,4807.1 3610.52,4835.46
  region net $1N482: 4782.96,4876.56 4799.54,4839.76 4819.54,4839.76 4836.11,4876.56
  region net NSLEEP: 4782.96,4595.1 4804.54,4558.3 4814.54,4558.3 4836.11,4595.1
  region net AOUT+OUT: 5984.5,3593.25 5952.3,3585 5952.3,3555 5984.5,3546.75
  region net ADC-3: 5984.5,3693.25 5952.3,3685 5952.3,3655 5984.5,3646.75
  region net ADC-2: 5984.17,3792.96 5952.09,3784.57 5952.51,3754.57 5984.82,3746.47
  region net ADC-1: 5984.17,3892.96 5952.09,3884.57 5952.51,3854.57 5984.82,3846.47
  region net ADC-0: 5929,3984.57 5929,3954.57 5974,3939 5974,4001
  region net ADC-3: 5816.26,3646.61 5848.34,3655 5847.93,3685 5815.61,3693.1
  region net ADC-2: 5815.94,3746.32 5848.14,3754.57 5848.14,3784.57 5815.94,3792.82
  region net ADC-1: 5815.94,3846.32 5848.14,3854.57 5848.14,3884.57 5815.94,3892.82
  region net ADC-0: 5871.44,3984.57 5826.44,4000.57 5826.44,3938.57 5871.44,3954.57
  region net VCC10V: 3532.5,3495.16 3540,3464 3570,3464 3577.5,3495.16
  region net VCC: 5860.12,4433.76 5830.2,4375.55 5865.55,4340.2 5923.76,4370.12
  region net $1N34558: 4813.74,3468.27 4816.72,3454.9 4826.72,3452.79 4831.36,3464.56
  region net $1N34558: 4830.72,3334.66 4826.72,3347.13 4816.72,3347.13 4812.71,3334.66
  region net NSLEEP: 4860.28,3239.22 4856.27,3251.69 4846.27,3251.69 4842.27,3239.22

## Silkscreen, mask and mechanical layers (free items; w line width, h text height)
Mechanical 1:
  circle w1 net "": c3355,4850 r59.06
  circle w1 net "": c6220,4850 r59.06
  circle w1 net "": c6215,3355 r59.06
  circle w1 net "": c3350,3355 r59.06
  lines w10 net "": 3355,4665 cw(c3344.63,4508.49) 3500,4530 3495,3645 cw(c3375.39,3660.62) 3375,3540 3351.28,3540 ccw(c3350.64,3347.5) 3350,3155 3600,3155 5977.33,3155 ; 3356.28,4665 cw(c3355.64,4857.5) 3355,5050 3590,5050 5955,5050 ; 5950,5050 6220,5050 cw(c6219.36,4857.5) 6218.72,4665 ; 5980,3155 6215,3155 ccw(c6215,3347.5) 6215,3540 ; 6194.58,4665 6219.36,4665 ; 6195,4665 ccw(c6194.58,4545.3) 6075,4540 6070,3625 ccw(c6164.54,3635.43) 6160.79,3540.39 6213.96,3540.39 ; 5977.36,3154.96 5977.33,3155 ; 5977.36,3154.96 5977.33,3155 ; 5977.36,3154.96 5977.33,3155 ; 6213.96,3540.39 6214.36,3540 6213.96,3540.39 ; 6219.36,4665 6219.36,4665 ; 6219.36,4665 6219.36,4665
